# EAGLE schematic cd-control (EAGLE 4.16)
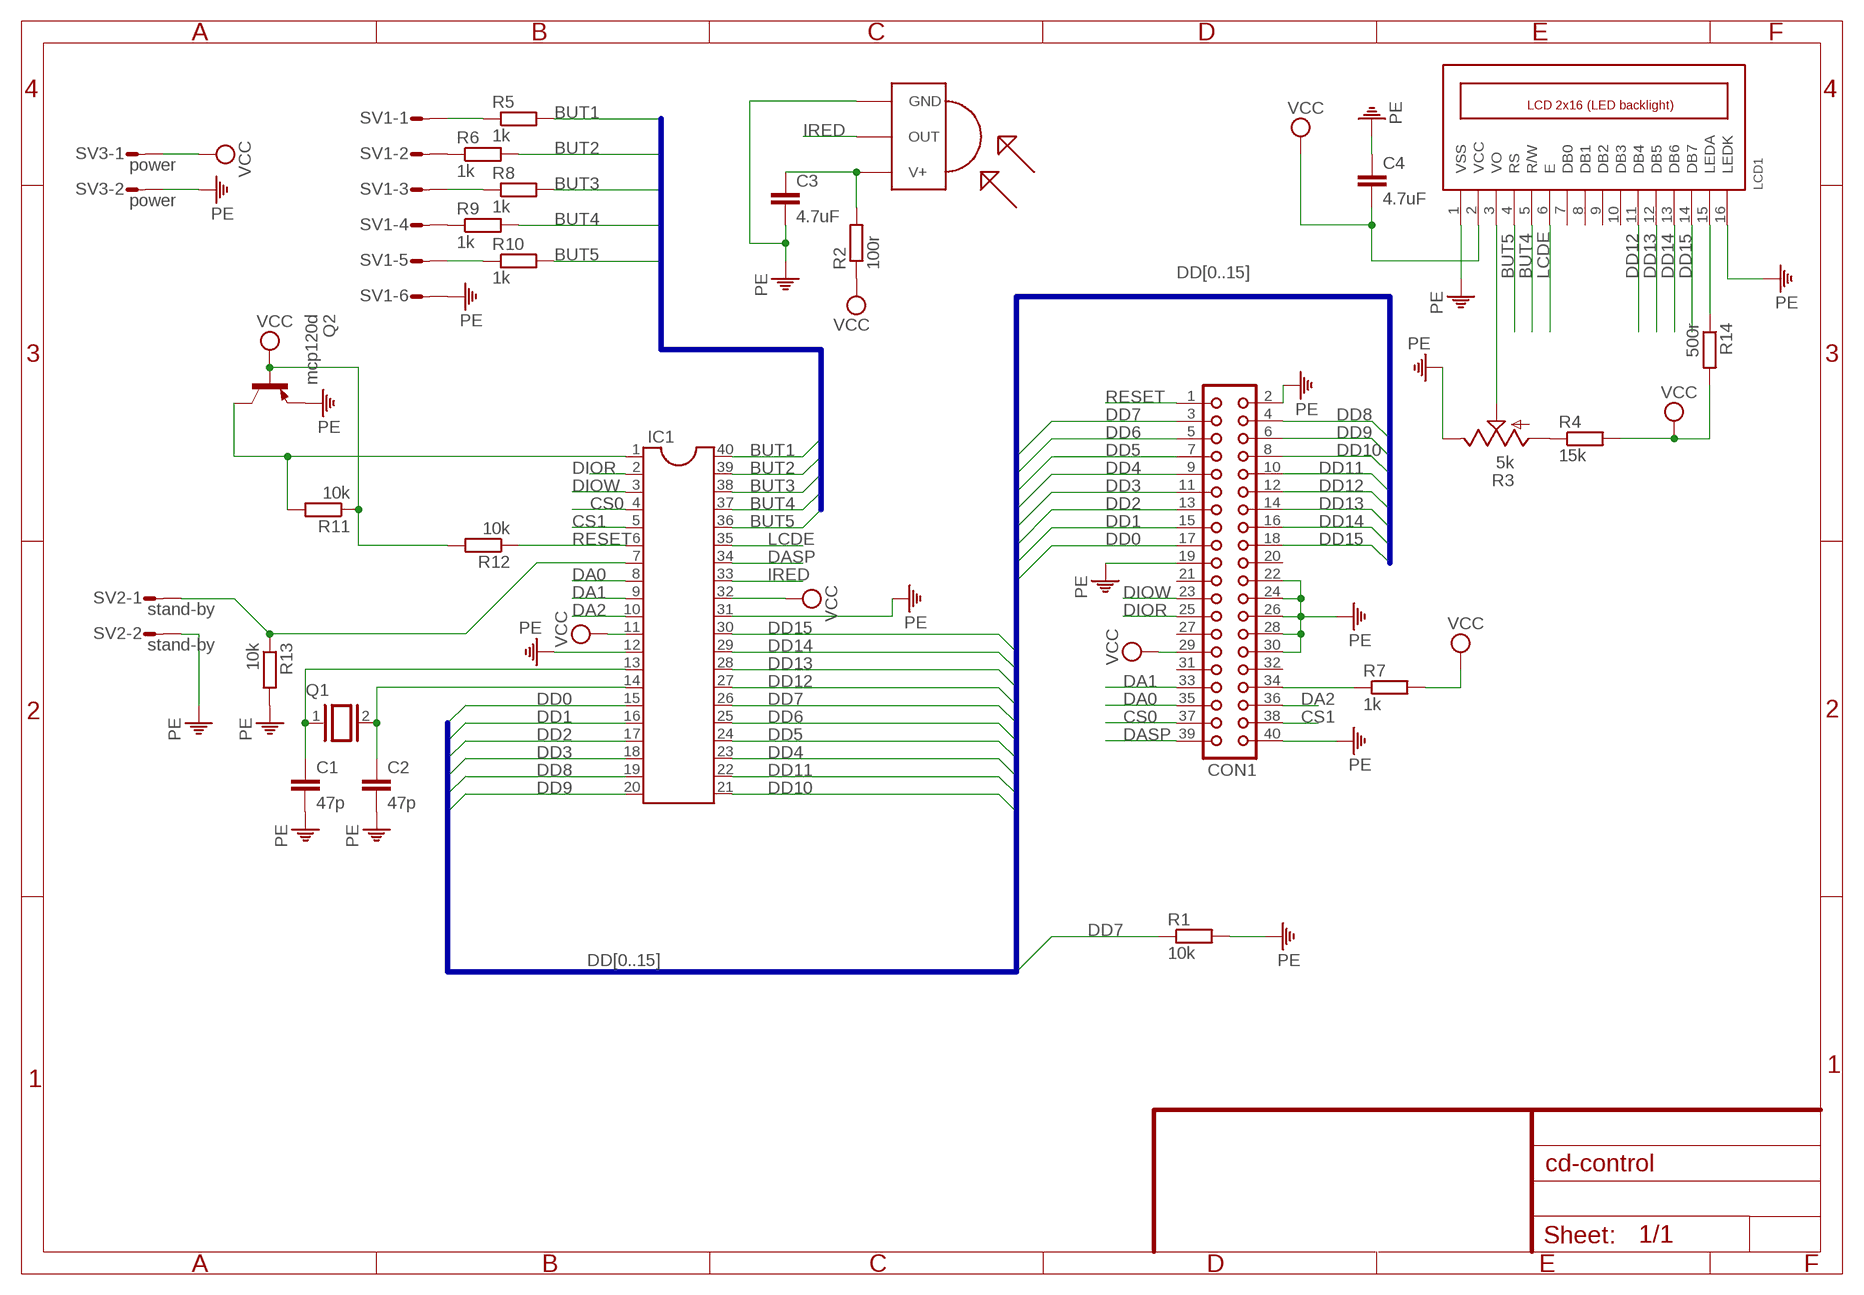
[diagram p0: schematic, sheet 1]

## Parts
C1  47p  C2,5-3  [C2.5-3]
C2  47p  C2,5-3  [C2.5-3]
C3  4.7uF  C2,5-3  [C2.5-3]
C4  4.7uF  C2,5-3  [C2.5-3]
CON1  CON40  [CON40]
IC1  DIL40  [DIL40]
LCD1  LCD_2X16_SIL  [HY-1602F]
Q1  XTAL  [Q]
Q2  mcp120d  2N3906  [TO92]
R1  10k  R-EU_0204/7  [0204/7]
R2  100r  R-EU_0204/7  [0204/7]
R3  5k  TRIM_US-S63X  [S63X]
R4  15k  R-EU_0207/15  [0207/15]
R5  1k  R-EU_0204/7  [0204/7]
R6  1k  R-EU_0204/7  [0204/7]
R7  1k  R-EU_0204/7  [0204/7]
R8  1k  R-EU_0207/15  [0207/15]
R9  1k  R-EU_0204/7  [0204/7]
R10  1k  R-EU_0204/7  [0204/7]
R11  10k  R-EU_0204/7  [0204/7]
R12  10k  R-EU_0207/15  [0207/15]
R13  10k  R-EU_0204/7  [0204/7]
R14  500r  R-EU_0204/7  [0204/7]
SV1  L06P  [L06P]
SV2  stand-by  L02P  [L02P]
SV3  power  L02P  [L02P]
U$1  TSOP1736  [TSOP17XX]

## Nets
BUT1: IC1.40 R5.2
BUT2: IC1.39 R6.2
BUT3: IC1.38 R8.2
BUT4: IC1.37 LCD1.5(R/W) R9.2
BUT5: IC1.36 LCD1.4(RS) R10.2
CS0: CON1.37 IC1.4
CS1: CON1.38 IC1.5
DA0: CON1.35 IC1.8
DA1: CON1.33 IC1.9
DA2: CON1.36 IC1.10
DASP: CON1.39 IC1.34
DD0: CON1.17 IC1.15
DD1: CON1.15 IC1.16
DD2: CON1.13 IC1.17
DD3: CON1.11 IC1.18
DD4: CON1.9 IC1.23
DD5: CON1.7 IC1.24
DD6: CON1.5 IC1.25
DD7: CON1.3 IC1.26 R1.1
DD8: CON1.4 IC1.19
DD9: CON1.6 IC1.20
DD10: CON1.8 IC1.21
DD11: CON1.10 IC1.22
DD12: CON1.12 IC1.27 LCD1.11(DB4)
DD13: CON1.14 IC1.28 LCD1.12(DB5)
DD14: CON1.16 IC1.29 LCD1.13(DB6)
DD15: CON1.18 IC1.30 LCD1.14(DB7)
DIOR: CON1.25 IC1.2
DIOW: CON1.23 IC1.3
IRED: IC1.33 U$1.OUT
LCDE: IC1.35 LCD1.6(E)
N$1: C3.1 R2.2 U$1.V+
N$2: IC1.1 Q2.1(C) R11.2
N$3: R5.1 SV1.1
N$4: LCD1.3(VO) R3.S
N$5: R3.A R4.1
N$6: R6.1 SV1.2
N$7: C1.1 IC1.13 Q1.1
N$8: C2.1 IC1.14 Q1.2
N$9: CON1.34 R7.1
N$10: R8.1 SV1.3
N$11: R9.1 SV1.4
N$12: R10.1 SV1.5
N$13: LCD1.15(LEDA) R14.1
N$14: IC1.7 R13.1 SV2.1
PE: C1.2 C2.2 C3.2 C4.1 CON1.2 CON1.19 CON1.22 CON1.24 CON1.26 CON1.28 CON1.30 CON1.40 IC1.12 IC1.31 LCD1.1(VSS) LCD1.16(LEDK) Q2.3(E) R1.2 R3.E R13.2 SV1.6 SV2.2 SV3.2 U$1.GND
RESET: CON1.1 IC1.6 R12.1
VCC: C4.2 CON1.29 IC1.11 IC1.32 LCD1.2(VCC) Q2.2(B) R2.1 R4.2 R7.2 R11.1 R12.2 R14.2 SV3.1
Unconnected: CON1.20 CON1.21 CON1.27 CON1.31 CON1.32 LCD1.7(DB0) LCD1.8(DB1) LCD1.9(DB2) LCD1.10(DB3)

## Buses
DD[0..15]
BUT[1..5]

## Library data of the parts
C1-C4 = capacitor-wima:C: CAPACITOR
CON1 = con-harting:CON40: CONNECTOR
IC1 = ic-package:DIL40: Dual In Line
LCD1 = lcd_2x16_led_backlight:LCD_2X16_SIL
Q1 = special:XTAL: CRYSTAL
Q2 = transistor-pnp:2N3906: PNP Transistor
R1 R2 R4-R14 = rcl:R-EU_: RESISTOR, European symbol
R3 = pot:TRIM_US-: POTENTIOMETER
SV1 = con-amp-mt:L06P: AMP MT CONNECTOR
SV2 SV3 = con-amp-mt:L02P: AMP MT CONNECTOR
U$1 = tsop:TSOP1736: IR Receiver and Demodulator

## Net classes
0 default: width 0.508 mm, drill 0.381 mm, clearance 0.813 mm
